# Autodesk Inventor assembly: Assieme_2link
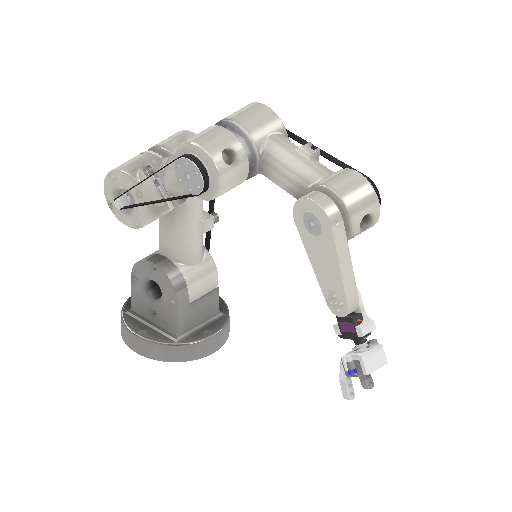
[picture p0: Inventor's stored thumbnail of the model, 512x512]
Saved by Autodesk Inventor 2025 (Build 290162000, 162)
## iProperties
Created: 2025-06
Part Number: Assieme_2link
Document SubType Name: Assembly
Designer: Ryzen5700u
Author: Ryzen5700u
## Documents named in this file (8)
- C:\Users\R5800u\Desktop\robot v3\Assieme_2link.iam
- C:\Users\R5800u\Desktop\robot v3\Assieme_link.iam
- C:\Users\R5800u\Desktop\robot v3\blocco_base.ipt
- C:\Users\R5800u\Desktop\robot v3\braccio finale.ipt
- C:\Users\R5800u\Desktop\robot v3\Assieme_pinza_m5_2gdl_MG90.iam
- C:\Users\R5800u\Desktop\robot v3\blocco_quadrato.ipt
- C:\Users\R5800u\Documents\Inventor\Content Center Files\R2025\it-IT\AS 1420\AS 1420 - 1973 - M3 x 6.ipt
- C:\Users\R5800u\Documents\Inventor\Content Center Files\R2025\it-IT\AS 1112 (2)\AS 1112 - M3  Tipo 5.ipt
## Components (10 placed, 7 different names)
1. Assieme_link:1 [sub-assembly] — Coincidente:7, Coincidente:8, Coincidente:9, Coincidente:14, Coincidente:15, Coincidente:23
2. blocco_base:1 — Coincidente:7, Coincidente:8, Coincidente:9
3. braccio finale:1 — Rotazionale:2, Coincidente:21
4. Assieme_pinza_m5_2gdl_MG90:1 [sub-assembly]
5. Assieme_link:2 [sub-assembly] — Coincidente:10, Coincidente:12, Coincidente:13, Coincidente:14, Angolo:2, Coincidente:16, Coincidente:20
6. blocco_quadrato:1 — Coincidente:10, Coincidente:12, Coincidente:13, Coincidente:15
7. Assieme_link:3 [sub-assembly] — Coincidente:16, Coincidente:17, Coincidente:18, Coincidente:19, Rotazionale:2, Coincidente:21
8. blocco_quadrato:2 — Coincidente:17, Coincidente:18, Coincidente:19, Coincidente:20
9. AS 1420 - Metrico M3 x 6:1
10. AS 1112 (2) - Metrico M3  Tipo 5:1 — Coincidente:23
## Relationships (17: Mate 15, Angle 1, RevoluteJoint 1)
- Coincidente:7 [Mate]: Assieme_link:1 ↔ blocco_base:1
- Coincidente:8 [Mate]: Assieme_link:1 ↔ blocco_base:1
- Coincidente:9 [Mate]: Assieme_link:1 ↔ blocco_base:1
- Coincidente:10 [Mate]: Assieme_link:2 ↔ blocco_quadrato:1
- Coincidente:12 [Mate]: Assieme_link:2 ↔ blocco_quadrato:1
- Coincidente:13 [Mate]: Assieme_link:2 ↔ blocco_quadrato:1
- Coincidente:14 [Mate]: Assieme_link:1 ↔ Assieme_link:2
- Coincidente:15 [Mate]: Assieme_link:1 ↔ blocco_quadrato:1
- Angolo:2 [Angle]: Assieme_link:2
- Coincidente:16 [Mate]: Assieme_link:2 ↔ Assieme_link:3
- Coincidente:17 [Mate]: Assieme_link:3 ↔ blocco_quadrato:2
- Coincidente:18 [Mate]: Assieme_link:3 ↔ blocco_quadrato:2
- Coincidente:19 [Mate]: Assieme_link:3 ↔ blocco_quadrato:2
- Coincidente:20 [Mate]: Assieme_link:2 ↔ blocco_quadrato:2
- Rotazionale:2 [RevoluteJoint]: braccio finale:1 ↔ Assieme_link:3
- Coincidente:21 [Mate]: braccio finale:1 ↔ Assieme_link:3
- Coincidente:23 [Mate]: Assieme_link:1 ↔ AS 1112 (2) - Metrico M3  Tipo 5:1
